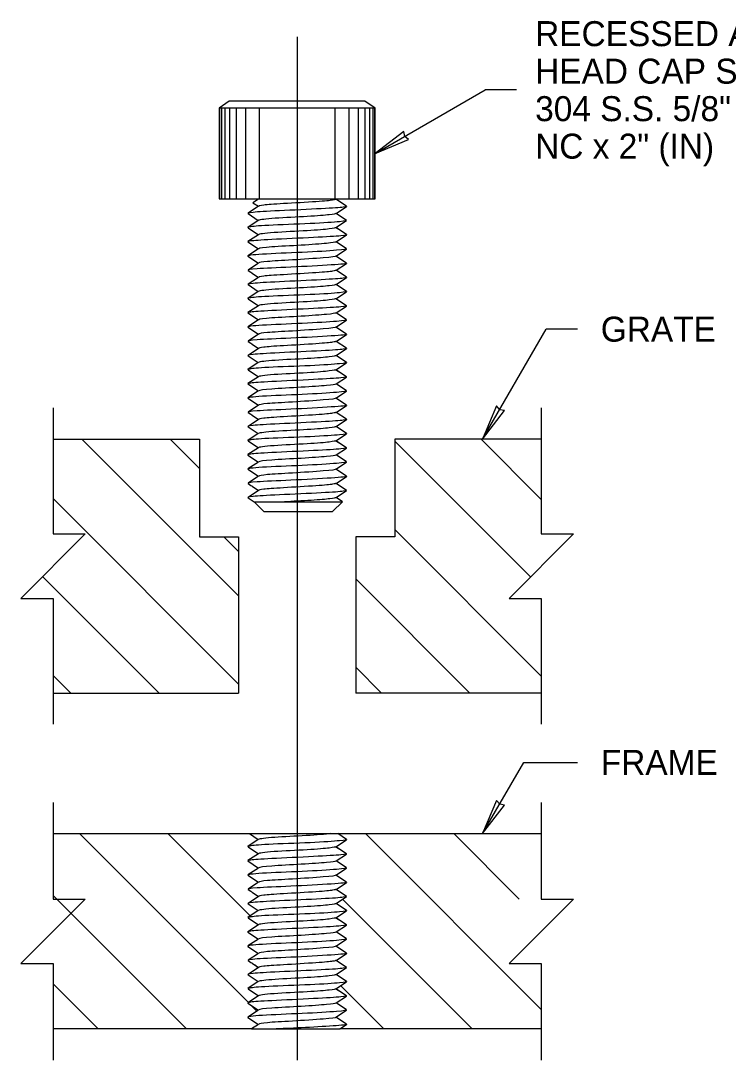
# Model space of a CAD drawing. Extents: x 99862 to 103151, y 100000 to 102076.
# Drawn here: x 102399 to 102852, y 100943 to 101608 of the extents above; entities that cross this region are included whole.
import ezdxf

# ---------------------------------------------------------------- set-up
doc = ezdxf.new("R2010")
doc.units = 0
for name, color, linetype in [('Level 1', 7, 'Continuous'), ('Level 14', 7, 'Continuous'), ('Level 15', 7, 'Continuous'), ('Level 17', 7, 'Continuous'), ('Level 2', 7, 'Continuous'), ('Level 20', 7, 'Continuous')]:
    doc.layers.add(name, color=color, linetype=linetype)

msp = doc.modelspace()

# ---------------------------------------------------------------- linework, layer by layer
at = {"layer": 'Level 1'}
for p, q in [((102551.08, 101084.06), (102544.4, 101079.63)), ((102545.39, 101087.88), (102551.08, 101084.06)), ((102600.77, 101079.5), (102607.5, 101083.97)), ((102607.5, 101084.12), (102601.89, 101087.88)), ((102544.56, 101079.39), (102551.11, 101075)), ((102607.44, 101075.02), (102600.77, 101079.5)), ((102551.11, 101075), (102544.44, 101070.59)), ((102600.83, 101070.41), (102607.5, 101074.81)), ((102544.44, 101070.37), (102551.14, 101065.88)), ((102551.14, 101065.88), (102544.44, 101061.42)), ((102600.78, 101061.28), (102607.5, 101065.79)), ((102607.5, 101065.93), (102600.83, 101070.41)), ((102544.44, 101061.21), (102551.11, 101056.73)), ((102607.5, 101056.77), (102600.78, 101061.28)), ((102551.11, 101056.73), (102544.5, 101052.33)), ((102600.89, 101052.19), (102607.5, 101056.62)), ((102607.5, 101047.75), (102600.89, 101052.19)), ((102551.14, 101047.7), (102544.5, 101043.24)), ((102600.83, 101043.13), (102607.5, 101047.61)), ((102551.08, 101038.61), (102544.4, 101034.17)), ((102544.5, 101043.02), (102551.08, 101038.61)), ((102600.77, 101034.04), (102607.5, 101038.52)), ((102607.5, 101038.66), (102600.83, 101043.13)), ((102544.56, 101033.93), (102551.11, 101029.54)), ((102607.44, 101029.57), (102600.77, 101034.04)), ((102551.11, 101029.54), (102544.44, 101025.13)), ((102544.44, 101024.92), (102551.14, 101020.42)), ((102600.83, 101024.95), (102607.5, 101029.35)), ((102607.5, 101020.48), (102600.83, 101024.95)), ((102551.14, 101020.42), (102544.44, 101015.97)), ((102600.78, 101015.82), (102607.5, 101020.33)), ((102544.44, 101015.75), (102551.11, 101011.27)), ((102551.11, 101011.27), (102544.5, 101006.88)), ((102607.5, 101011.32), (102600.78, 101015.82)), ((102600.89, 101006.73), (102607.5, 101011.17)), ((102607.5, 101002.3), (102600.89, 101006.73)), ((102551.14, 101002.24), (102544.5, 100997.79)), ((102544.5, 100997.57), (102551.08, 100993.16)), ((102600.83, 100997.68), (102607.5, 101002.15)), ((102607.5, 100993.21), (102600.83, 100997.68)), ((102551.08, 100993.16), (102544.4, 100988.72)), ((102600.77, 100988.59), (102607.5, 100993.06)), ((102551.11, 100984.09), (102544.44, 100979.68)), ((102544.56, 100988.48), (102551.11, 100984.09)), ((102607.44, 100984.12), (102600.77, 100988.59)), ((102544.44, 100979.46), (102551.14, 100974.97)), ((102600.83, 100979.5), (102607.5, 100983.9)), ((102607.5, 100975.02), (102600.83, 100979.5)), ((102551.14, 100974.97), (102544.44, 100970.52)), ((102600.78, 100970.37), (102607.5, 100974.88)), ((102544.44, 100970.3), (102551.11, 100965.82)), ((102551.11, 100965.82), (102546.69, 100962.88)), ((102607.5, 100965.86), (102600.78, 100970.37)), ((102603.27, 100962.88), (102607.5, 100965.72))]:
    msp.add_line(p, q, dxfattribs=at)
for points in [[(102544.5, 101052.12), (102546.21, 101050.95), (102546.84, 101050.59)], [(102547.09, 101050.37), (102551.14, 101047.7)], [(102544.5, 101006.66), (102546.21, 101005.5), (102546.84, 101005.13)], [(102547.09, 101004.92), (102551.14, 101002.24)]]:
    msp.add_lwpolyline(points, dxfattribs=at)
at = {"layer": 'Level 14'}
for p, q in [((102532.52, 101556.63), (102525.94, 101552.22)), ((102625.94, 101552.22), (102619.36, 101556.63)), ((102625.94, 101552.22), (102525.94, 101552.22)), ((102526.33, 101552.22), (102526.33, 101494.13)), ((102527.53, 101552.22), (102527.53, 101494.13)), ((102529.59, 101552.22), (102529.59, 101494.13)), ((102532.64, 101552.22), (102532.64, 101494.13)), ((102536.91, 101552.22), (102536.91, 101494.13)), ((102542.87, 101552.22), (102542.87, 101494.13)), ((102551.73, 101552.22), (102551.73, 101494.13)), ((102600.14, 101552.22), (102600.14, 101494.13)), ((102609.01, 101552.22), (102609.01, 101494.13)), ((102614.97, 101552.22), (102614.97, 101494.13)), ((102619.24, 101552.22), (102619.24, 101494.13)), ((102622.29, 101552.22), (102622.29, 101494.13)), ((102624.35, 101552.22), (102624.35, 101494.13)), ((102625.55, 101552.22), (102625.55, 101494.13)), ((102551.14, 101493.95), (102547.66, 101491.62)), ((102600.67, 101493.95), (102551.14, 101493.95)), ((102607.5, 101489.37), (102600.67, 101493.95)), ((102551.14, 101489.32), (102544.5, 101484.86)), ((102544.5, 101484.64), (102551.08, 101480.23)), ((102600.83, 101484.75), (102607.5, 101489.23)), ((102607.5, 101480.28), (102600.83, 101484.75)), ((102551.08, 101480.23), (102544.37, 101475.77)), ((102600.77, 101475.66), (102607.5, 101480.13)), ((102551.11, 101471.16), (102544.44, 101466.75)), ((102544.56, 101475.55), (102551.11, 101471.16)), ((102607.44, 101471.19), (102600.77, 101475.66)), ((102600.83, 101466.57), (102607.5, 101470.97)), ((102544.44, 101466.53), (102551.14, 101462.04)), ((102607.5, 101462.1), (102600.83, 101466.57)), ((102551.14, 101462.04), (102544.44, 101457.59)), ((102544.44, 101457.37), (102551.11, 101452.89)), ((102600.78, 101457.44), (102607.5, 101461.95)), ((102607.5, 101452.93), (102600.78, 101457.44)), ((102551.11, 101452.89), (102544.5, 101448.5)), ((102600.89, 101448.35), (102607.5, 101452.79)), ((102551.14, 101443.86), (102544.5, 101439.41)), ((102600.83, 101439.3), (102607.5, 101443.77)), ((102607.5, 101443.92), (102600.89, 101448.35)), ((102544.5, 101439.19), (102551.08, 101434.77)), ((102607.5, 101434.83), (102600.83, 101439.3)), ((102551.08, 101434.77), (102544.37, 101430.32)), ((102544.56, 101430.1), (102551.11, 101425.7)), ((102600.77, 101430.21), (102607.5, 101434.68)), ((102607.44, 101425.73), (102600.77, 101430.21)), ((102551.11, 101425.7), (102544.44, 101421.3)), ((102600.83, 101421.12), (102607.5, 101425.52)), ((102544.44, 101421.08), (102551.14, 101416.59)), ((102551.14, 101416.59), (102544.44, 101412.13)), ((102600.78, 101411.99), (102607.5, 101416.5)), ((102607.5, 101416.64), (102600.83, 101421.12)), ((102544.44, 101411.92), (102551.11, 101407.44)), ((102607.5, 101407.48), (102600.78, 101411.99)), ((102551.11, 101407.44), (102544.5, 101403.04)), ((102600.89, 101402.9), (102607.5, 101407.33)), ((102551.14, 101398.41), (102544.5, 101393.95)), ((102600.83, 101393.84), (102607.5, 101398.32)), ((102607.5, 101398.46), (102600.89, 101402.9)), ((102544.5, 101393.73), (102551.08, 101389.32)), ((102607.5, 101389.37), (102600.83, 101393.84)), ((102551.08, 101389.32), (102544.37, 101384.86)), ((102544.56, 101384.64), (102551.11, 101380.25)), ((102600.77, 101384.75), (102607.5, 101389.23)), ((102607.44, 101380.28), (102600.77, 101384.75)), ((102551.11, 101380.25), (102544.44, 101375.84)), ((102600.83, 101375.66), (102607.5, 101380.06)), ((102544.44, 101375.63), (102551.14, 101371.13)), ((102551.14, 101371.13), (102544.44, 101366.68)), ((102600.78, 101366.53), (102607.5, 101371.04)), ((102607.5, 101371.19), (102600.83, 101375.66)), ((102544.44, 101366.46), (102551.11, 101361.98)), ((102607.5, 101362.03), (102600.78, 101366.53)), ((102551.11, 101361.98), (102544.5, 101357.59)), ((102600.89, 101357.44), (102607.5, 101361.88)), ((102607.5, 101353.01), (102600.89, 101357.44)), ((102551.14, 101352.95), (102544.5, 101348.5)), ((102600.83, 101348.39), (102607.5, 101352.86)), ((102551.08, 101343.87), (102544.37, 101339.41)), ((102544.5, 101348.28), (102551.08, 101343.87)), ((102600.77, 101339.3), (102607.5, 101343.77)), ((102607.5, 101343.92), (102600.83, 101348.39)), ((102544.56, 101339.19), (102551.11, 101334.8)), ((102607.44, 101334.83), (102600.77, 101339.3)), ((102551.11, 101334.8), (102544.44, 101330.39)), ((102544.44, 101330.17), (102551.14, 101325.68)), ((102600.83, 101330.21), (102607.5, 101334.61)), ((102607.5, 101325.73), (102600.83, 101330.21)), ((102551.14, 101325.68), (102544.44, 101321.23)), ((102600.78, 101321.08), (102607.5, 101325.59)), ((102544.44, 101321.01), (102551.11, 101316.53)), ((102607.5, 101316.57), (102600.78, 101321.08)), ((102551.11, 101316.53), (102544.5, 101312.13)), ((102600.89, 101311.99), (102607.5, 101316.43)), ((102607.5, 101307.55), (102600.89, 101311.99)), ((102551.14, 101307.5), (102544.5, 101303.04)), ((102600.83, 101302.93), (102607.5, 101307.41)), ((102544.5, 101302.83), (102548.41, 101300.2)), ((102548.41, 101300.2), (102604.91, 101300.2)), ((102554.66, 101293.95), (102548.41, 101300.2)), ((102598.66, 101293.95), (102604.91, 101300.2)), ((102604.91, 101300.2), (102600.83, 101302.93)), ((102545.39, 101087.88), (102601.89, 101087.88)), ((102546.69, 100962.88), (102603.27, 100962.88))]:
    msp.add_line(p, q, dxfattribs=at)
for points in [[(102619.36, 101556.63), (102532.52, 101556.63)], [(102525.94, 101552.22), (102525.94, 101494.13), (102551.73, 101494.13)], [(102625.94, 101494.13), (102625.94, 101552.22)], [(102547.66, 101491.62), (102551.14, 101489.32)], [(102600.94, 101494.13), (102625.94, 101494.13)], [(102600.86, 101475.6), (102602.38, 101474.61)], [(102544.5, 101448.28), (102546.21, 101447.12), (102546.84, 101446.75), (102547.09, 101446.53), (102551.14, 101443.86)], [(102600.86, 101430.15), (102602.38, 101429.15)], [(102544.5, 101402.83), (102546.21, 101401.66), (102546.84, 101401.3), (102547.09, 101401.08), (102551.14, 101398.41)], [(102600.86, 101384.7), (102602.38, 101383.7)], [(102544.5, 101357.37), (102546.21, 101356.21), (102546.84, 101355.84), (102547.09, 101355.63), (102551.14, 101352.95)], [(102600.86, 101339.24), (102602.38, 101338.24)], [(102544.5, 101311.92), (102546.21, 101310.75), (102546.84, 101310.39), (102547.09, 101310.17), (102551.14, 101307.5)], [(102554.66, 101293.95), (102598.66, 101293.95)], [(102600.86, 101079.44), (102602.38, 101078.44)], [(102600.86, 101033.99), (102602.38, 101032.99)], [(102600.86, 100988.53), (102602.38, 100987.53)]]:
    msp.add_lwpolyline(points, dxfattribs=at)
for points in [[(102600.67, 101493.73), (102600.67, 101493.73), (102599.98, 101493.3), (102590.74, 101492.35), (102564.93, 101490.9), (102552.91, 101490.1), (102551.46, 101489.52), (102551.33, 101489.44)], [(102607.5, 101489.37), (102607.63, 101489.3), (102607.5, 101488.79), (102594.79, 101487.84), (102561.83, 101486.39), (102545.19, 101485.44), (102544.25, 101484.79), (102544.5, 101484.64)], [(102600.61, 101484.64), (102600.48, 101484.57), (102598.39, 101483.99), (102584.16, 101482.75), (102559.68, 101481.73), (102551.9, 101480.72), (102551.27, 101480.35)], [(102607.5, 101480.28), (102607.76, 101480.13), (102605.86, 101479.55), (102586.37, 101478.17), (102554.05, 101477.15), (102543.93, 101476.06), (102544.31, 101475.55), (102544.37, 101475.55)], [(102607.5, 101471.19), (102607.76, 101471.04), (102606.43, 101470.46), (102589.03, 101469.44), (102556.26, 101467.92), (102544.25, 101467.12), (102544.31, 101466.61), (102544.44, 101466.53)], [(102600.61, 101475.55), (102600.48, 101475.48), (102598.39, 101474.9), (102584.16, 101473.66), (102558.86, 101472.57), (102551.14, 101471.55), (102551.14, 101471.12)], [(102600.61, 101466.46), (102600.29, 101466.24), (102596.94, 101465.66), (102579.29, 101464.35), (102557.4, 101463.33), (102551.84, 101462.53), (102551.33, 101462.17)], [(102607.5, 101462.1), (102607.88, 101461.88), (102604.28, 101461.23), (102580.18, 101459.77), (102550.51, 101458.68), (102543.8, 101457.81), (102544.44, 101457.37)], [(102600.73, 101457.44), (102600.8, 101457.08), (102595.1, 101456.43), (102571.95, 101454.83), (102554.87, 101454.03), (102551.71, 101453.3), (102551.39, 101453.08)], [(102607.5, 101452.93), (102608.07, 101452.57), (102601.05, 101451.92), (102570.81, 101450.24), (102547.28, 101449.37), (102544.06, 101448.57), (102544.5, 101448.28)], [(102607.5, 101443.92), (102607.63, 101443.84), (102607.5, 101443.33), (102594.79, 101442.39), (102561.83, 101440.93), (102545.19, 101439.99), (102544.25, 101439.33), (102544.5, 101439.19)], [(102600.67, 101448.28), (102600.67, 101448.28), (102599.98, 101447.84), (102590.74, 101446.9), (102564.93, 101445.44), (102552.91, 101444.64), (102551.46, 101444.06), (102551.33, 101443.99)], [(102600.61, 101439.19), (102600.48, 101439.12), (102598.39, 101438.53), (102584.16, 101437.3), (102559.68, 101436.28), (102551.9, 101435.26), (102551.27, 101434.9)], [(102607.5, 101434.83), (102607.76, 101434.68), (102605.86, 101434.1), (102586.37, 101432.72), (102554.05, 101431.7), (102543.93, 101430.61), (102544.31, 101430.1), (102544.37, 101430.1)], [(102600.61, 101430.1), (102600.48, 101430.03), (102598.39, 101429.44), (102584.16, 101428.21), (102558.86, 101427.12), (102551.14, 101426.1), (102551.14, 101425.66)], [(102607.5, 101425.73), (102607.76, 101425.59), (102606.43, 101425.01), (102589.03, 101423.99), (102556.26, 101422.46), (102544.25, 101421.66), (102544.31, 101421.15), (102544.44, 101421.08)], [(102607.5, 101416.64), (102607.88, 101416.43), (102604.28, 101415.77), (102580.18, 101414.32), (102550.51, 101413.23), (102543.8, 101412.35), (102544.44, 101411.92)], [(102600.61, 101421.01), (102600.29, 101420.79), (102596.94, 101420.21), (102579.29, 101418.9), (102557.4, 101417.88), (102551.84, 101417.08), (102551.33, 101416.72)], [(102600.73, 101411.99), (102600.8, 101411.63), (102595.1, 101410.97), (102571.95, 101409.37), (102554.87, 101408.57), (102551.71, 101407.84), (102551.39, 101407.63)], [(102607.5, 101407.48), (102608.07, 101407.12), (102601.05, 101406.46), (102570.81, 101404.79), (102547.28, 101403.92), (102544.06, 101403.12), (102544.5, 101402.83)], [(102607.5, 101398.46), (102607.63, 101398.39), (102607.5, 101397.88), (102594.79, 101396.93), (102561.83, 101395.48), (102545.19, 101394.53), (102544.25, 101393.88), (102544.5, 101393.73)], [(102600.67, 101402.83), (102600.67, 101402.83), (102599.98, 101402.39), (102590.74, 101401.44), (102564.93, 101399.99), (102552.91, 101399.19), (102551.46, 101398.61), (102551.33, 101398.53)], [(102600.61, 101393.73), (102600.48, 101393.66), (102598.39, 101393.08), (102584.16, 101391.84), (102559.68, 101390.83), (102551.9, 101389.81), (102551.27, 101389.44)], [(102607.5, 101389.37), (102607.76, 101389.23), (102605.86, 101388.64), (102586.37, 101387.26), (102554.05, 101386.24), (102543.93, 101385.15), (102544.31, 101384.64), (102544.37, 101384.64)], [(102600.61, 101384.64), (102600.48, 101384.57), (102598.39, 101383.99), (102584.16, 101382.75), (102558.86, 101381.66), (102551.14, 101380.64), (102551.14, 101380.21)], [(102607.5, 101380.28), (102607.76, 101380.13), (102606.43, 101379.55), (102589.03, 101378.53), (102556.26, 101377.01), (102544.25, 101376.21), (102544.31, 101375.7), (102544.44, 101375.63)], [(102607.5, 101371.19), (102607.88, 101370.97), (102604.28, 101370.32), (102580.18, 101368.86), (102550.51, 101367.77), (102543.8, 101366.9), (102544.44, 101366.46)], [(102600.61, 101375.55), (102600.29, 101375.33), (102596.94, 101374.75), (102579.29, 101373.44), (102557.4, 101372.43), (102551.84, 101371.63), (102551.33, 101371.26)], [(102600.73, 101366.53), (102600.8, 101366.17), (102595.1, 101365.52), (102571.95, 101363.92), (102554.87, 101363.12), (102551.71, 101362.39), (102551.39, 101362.17)], [(102607.5, 101362.03), (102608.07, 101361.66), (102601.05, 101361.01), (102570.81, 101359.33), (102547.28, 101358.46), (102544.06, 101357.66), (102544.5, 101357.37)], [(102600.67, 101357.37), (102600.67, 101357.37), (102599.98, 101356.93), (102590.74, 101355.99), (102564.93, 101354.53), (102552.91, 101353.73), (102551.46, 101353.15), (102551.33, 101353.08)], [(102607.5, 101353.01), (102607.63, 101352.93), (102607.5, 101352.43), (102594.79, 101351.48), (102561.83, 101350.03), (102545.19, 101349.08), (102544.25, 101348.43), (102544.5, 101348.28)], [(102607.5, 101343.92), (102607.76, 101343.77), (102605.86, 101343.19), (102586.37, 101341.81), (102554.05, 101340.79), (102543.93, 101339.7), (102544.31, 101339.19), (102544.37, 101339.19)], [(102600.61, 101348.28), (102600.48, 101348.21), (102598.39, 101347.63), (102584.16, 101346.39), (102559.68, 101345.37), (102551.9, 101344.35), (102551.27, 101343.99)], [(102600.61, 101339.19), (102600.48, 101339.12), (102598.39, 101338.53), (102584.16, 101337.3), (102558.86, 101336.21), (102551.14, 101335.19), (102551.14, 101334.75)], [(102607.5, 101334.83), (102607.76, 101334.68), (102606.43, 101334.1), (102589.03, 101333.08), (102556.26, 101331.55), (102544.25, 101330.75), (102544.31, 101330.24), (102544.44, 101330.17)], [(102600.61, 101330.1), (102600.29, 101329.88), (102596.94, 101329.3), (102579.29, 101327.99), (102557.4, 101326.97), (102551.84, 101326.17), (102551.33, 101325.81)], [(102607.5, 101325.73), (102607.88, 101325.52), (102604.28, 101324.86), (102580.18, 101323.41), (102550.51, 101322.32), (102543.8, 101321.44), (102544.44, 101321.01)], [(102600.73, 101321.08), (102600.8, 101320.72), (102595.1, 101320.06), (102571.95, 101318.46), (102554.87, 101317.66), (102551.71, 101316.93), (102551.39, 101316.72)], [(102607.5, 101316.57), (102608.07, 101316.21), (102601.05, 101315.55), (102570.81, 101313.88), (102547.28, 101313.01), (102544.06, 101312.21), (102544.5, 101311.92)], [(102600.67, 101311.92), (102600.67, 101311.92), (102599.98, 101311.48), (102590.74, 101310.53), (102564.93, 101309.08), (102552.91, 101308.28), (102551.46, 101307.7), (102551.33, 101307.63)], [(102607.5, 101307.55), (102607.63, 101307.48), (102607.5, 101306.97), (102594.79, 101306.03), (102561.83, 101304.57), (102545.19, 101303.63), (102544.25, 101302.97), (102544.5, 101302.83)], [(102600.61, 101302.83), (102600.48, 101302.75), (102598.39, 101302.17), (102586.22, 101301.11), (102572.72, 101300.47), (102567.84, 101300.2)], [(102607.5, 101084.12), (102607.76, 101083.97), (102605.86, 101083.39), (102586.37, 101082.01), (102554.05, 101080.99), (102543.93, 101079.9), (102544.31, 101079.39), (102544.37, 101079.39)], [(102597.49, 101087.88), (102594.32, 101087.48), (102582.62, 101086.52), (102559.68, 101085.57), (102551.9, 101084.55), (102551.27, 101084.19)], [(102600.61, 101079.39), (102600.48, 101079.32), (102598.39, 101078.73), (102584.16, 101077.5), (102558.86, 101076.41), (102551.14, 101075.39), (102551.14, 101074.95)], [(102607.5, 101075.02), (102607.76, 101074.88), (102606.43, 101074.3), (102589.03, 101073.28), (102556.26, 101071.75), (102544.25, 101070.95), (102544.31, 101070.44), (102544.44, 101070.37)], [(102607.5, 101065.93), (102607.88, 101065.72), (102604.28, 101065.06), (102580.18, 101063.61), (102550.51, 101062.52), (102543.8, 101061.64), (102544.44, 101061.21)], [(102600.61, 101070.3), (102600.29, 101070.08), (102596.94, 101069.5), (102579.29, 101068.19), (102557.4, 101067.17), (102551.84, 101066.37), (102551.33, 101066.01)], [(102600.73, 101061.28), (102600.8, 101060.92), (102595.1, 101060.26), (102571.95, 101058.66), (102554.87, 101057.86), (102551.71, 101057.13), (102551.39, 101056.92)], [(102607.5, 101056.77), (102608.07, 101056.41), (102601.05, 101055.75), (102570.81, 101054.08), (102547.28, 101053.21), (102544.06, 101052.41), (102544.5, 101052.12)], [(102600.67, 101052.12), (102600.67, 101052.12), (102599.98, 101051.68), (102590.74, 101050.73), (102564.93, 101049.28), (102552.91, 101048.48), (102551.46, 101047.9), (102551.33, 101047.82)], [(102607.5, 101047.75), (102607.63, 101047.68), (102607.5, 101047.17), (102594.79, 101046.22), (102561.83, 101044.77), (102545.19, 101043.82), (102544.25, 101043.17), (102544.5, 101043.02)], [(102607.5, 101038.66), (102607.76, 101038.52), (102605.86, 101037.93), (102586.37, 101036.55), (102554.05, 101035.53), (102543.93, 101034.44), (102544.31, 101033.93), (102544.37, 101033.93)], [(102600.61, 101043.02), (102600.48, 101042.95), (102598.39, 101042.37), (102584.16, 101041.13), (102559.68, 101040.12), (102551.9, 101039.1), (102551.27, 101038.73)], [(102600.61, 101033.93), (102600.48, 101033.86), (102598.39, 101033.28), (102584.16, 101032.04), (102558.86, 101030.95), (102551.14, 101029.93), (102551.14, 101029.5)], [(102607.5, 101029.57), (102607.76, 101029.42), (102606.43, 101028.84), (102589.03, 101027.82), (102556.26, 101026.3), (102544.25, 101025.5), (102544.31, 101024.99), (102544.44, 101024.92)], [(102600.61, 101024.84), (102600.29, 101024.62), (102596.94, 101024.04), (102579.29, 101022.73), (102557.4, 101021.72), (102551.84, 101020.92), (102551.33, 101020.55)], [(102607.5, 101020.48), (102607.88, 101020.26), (102604.28, 101019.61), (102580.18, 101018.15), (102550.51, 101017.06), (102543.8, 101016.19), (102544.44, 101015.75)], [(102607.5, 101011.32), (102608.07, 101010.95), (102601.05, 101010.3), (102570.81, 101008.62), (102547.28, 101007.75), (102544.06, 101006.95), (102544.5, 101006.66)], [(102600.73, 101015.82), (102600.8, 101015.46), (102595.1, 101014.81), (102571.95, 101013.21), (102554.87, 101012.41), (102551.71, 101011.68), (102551.39, 101011.46)], [(102600.67, 101006.66), (102600.67, 101006.66), (102599.98, 101006.22), (102590.74, 101005.28), (102564.93, 101003.82), (102552.91, 101003.02), (102551.46, 101002.44), (102551.33, 101002.37)], [(102607.5, 101002.3), (102607.63, 101002.22), (102607.5, 101001.72), (102594.79, 101000.77), (102561.83, 100999.32), (102545.19, 100998.37), (102544.25, 100997.72), (102544.5, 100997.57)], [(102600.61, 100997.57), (102600.48, 100997.5), (102598.39, 100996.92), (102584.16, 100995.68), (102559.68, 100994.66), (102551.9, 100993.64), (102551.27, 100993.28)], [(102607.5, 100993.21), (102607.76, 100993.06), (102605.86, 100992.48), (102586.37, 100991.1), (102554.05, 100990.08), (102543.93, 100988.99), (102544.31, 100988.48), (102544.37, 100988.48)], [(102607.5, 100984.12), (102607.76, 100983.97), (102606.43, 100983.39), (102589.03, 100982.37), (102556.26, 100980.84), (102544.25, 100980.04), (102544.31, 100979.53), (102544.44, 100979.46)], [(102600.61, 100988.48), (102600.48, 100988.41), (102598.39, 100987.82), (102584.16, 100986.59), (102558.86, 100985.5), (102551.14, 100984.48), (102551.14, 100984.04)], [(102600.61, 100979.39), (102600.29, 100979.17), (102596.94, 100978.59), (102579.29, 100977.28), (102557.4, 100976.26), (102551.84, 100975.46), (102551.33, 100975.1)], [(102607.5, 100975.02), (102607.88, 100974.81), (102604.28, 100974.15), (102580.18, 100972.7), (102550.51, 100971.61), (102543.8, 100970.73), (102544.44, 100970.3)], [(102600.73, 100970.37), (102600.8, 100970.01), (102595.1, 100969.35), (102571.95, 100967.75), (102554.87, 100966.95), (102551.71, 100966.22), (102551.39, 100966.01)], [(102607.5, 100965.86), (102608.07, 100965.5), (102601.05, 100964.84), (102577.83, 100963.56), (102565.31, 100963.01), (102562.44, 100962.88)]]:
    msp.add_open_spline(points, degree=3, dxfattribs=at)
at = {"layer": 'Level 15'}
for p, q in [((102575.94, 101597.87), (102575.94, 100942.88)), ((102625.94, 101523.17), (102696.3, 101563.8)), ((102716.3, 101563.8), (102696.3, 101563.8)), ((102694.7, 101340.32), (102735.33, 101410.68)), ((102755.33, 101410.68), (102735.33, 101410.68)), ((102694.7, 101087.88), (102721.03, 101133.47)), ((102721.03, 101133.47), (102755.33, 101133.47))]:
    msp.add_line(p, q, dxfattribs=at)
for points in [[(102625.94, 101523.17), (102647.2, 101532), (102644.79, 101534.06), (102644.22, 101537.17)], [(102694.7, 101340.32), (102708.7, 101358.59), (102705.59, 101359.17), (102703.53, 101361.58)], [(102694.7, 101087.88), (102708.7, 101106.16), (102705.59, 101106.74), (102703.53, 101109.14)]]:
    msp.add_lwpolyline(points, close=True, dxfattribs=at)
for points in [[(102419.67, 101360.32), (102419.67, 101279.71), (102440.32, 101279.71), (102399.02, 101238.42), (102419.67, 101238.42), (102419.67, 101157.82)], [(102732.2, 101360.32), (102732.2, 101279.71), (102752.85, 101279.71), (102711.56, 101238.42), (102732.2, 101238.42), (102732.2, 101157.82)], [(102419.67, 101107.88), (102419.67, 101046.03), (102440.32, 101046.03), (102399.02, 101004.73), (102419.67, 101004.73), (102419.67, 100942.88)], [(102732.2, 101107.88), (102732.2, 101046.03), (102752.85, 101046.03), (102711.56, 101004.73), (102732.2, 101004.73), (102732.2, 100942.88)]]:
    msp.add_lwpolyline(points, dxfattribs=at)
at = {"layer": 'Level 17'}
for p, q in [((102538.44, 101240.05), (102438.17, 101340.32)), ((102513.44, 101321.62), (102494.74, 101340.32)), ((102725.29, 101252.15), (102638.44, 101339)), ((102732.2, 101301.8), (102693.69, 101340.32)), ((102538.44, 101183.48), (102419.67, 101302.25)), ((102538.44, 101268.33), (102528.96, 101277.82)), ((102732.2, 101188.67), (102638.44, 101282.43)), ((102487.53, 101177.82), (102412.98, 101252.37)), ((102686.49, 101177.82), (102613.44, 101250.87)), ((102629.92, 101177.82), (102613.44, 101194.3)), ((102430.97, 101177.82), (102419.67, 101189.11)), ((102436.62, 101087.88), (102544.71, 100979.79)), ((102493.19, 101087.88), (102546, 101035.07)), ((102619.65, 101087.88), (102732.2, 100975.33)), ((102676.22, 101087.88), (102718.07, 101046.03)), ((102419.67, 101048.26), (102505.06, 100962.88)), ((102605.02, 101045.94), (102688.08, 100962.88)), ((102548.96, 101003.83), (102550.79, 101001.99)), ((102419.67, 100991.7), (102448.49, 100962.88)), ((102603.84, 100990.56), (102631.52, 100962.88)), ((102546.09, 100978.41), (102550.2, 100974.31)), ((102419.67, 100963.41), (102420.2, 100962.88))]:
    msp.add_line(p, q, dxfattribs=at)
at = {"layer": 'Level 2'}
for p, q in [((102419.67, 101340.32), (102513.44, 101340.32)), ((102513.44, 101340.32), (102513.44, 101277.82)), ((102638.44, 101340.32), (102638.44, 101277.82)), ((102732.2, 101340.32), (102638.44, 101340.32)), ((102513.44, 101277.82), (102538.44, 101277.82)), ((102538.44, 101277.82), (102538.44, 101177.82)), ((102638.44, 101277.82), (102613.44, 101277.82)), ((102613.44, 101277.82), (102613.44, 101177.82)), ((102419.67, 101177.82), (102538.44, 101177.82)), ((102732.2, 101177.82), (102613.44, 101177.82)), ((102419.67, 101087.88), (102545.39, 101087.88)), ((102601.89, 101087.88), (102732.2, 101087.88)), ((102546.69, 100962.88), (102419.67, 100962.88)), ((102732.2, 100962.88), (102603.27, 100962.88))]:
    msp.add_line(p, q, dxfattribs=at)

# ---------------------------------------------------------------- texts
at = {"layer": 'Level 20'}
for s, p in [('RECESSED ALLEN', (102728.3, 101591.8)), ('HEAD CAP SCREW', (102728.3, 101567.8)), ('304 S.S. 5/8" (IN) - 11', (102728.3, 101543.8)), ('NC x 2" (IN)', (102728.3, 101519.8)), ('GRATE', (102770.32, 101402.69)), ('FRAME', (102770.32, 101125.47))]:
    msp.add_text(s, height=16, rotation=360, dxfattribs=at).set_placement(p)

doc.saveas('drawing.dxf')
